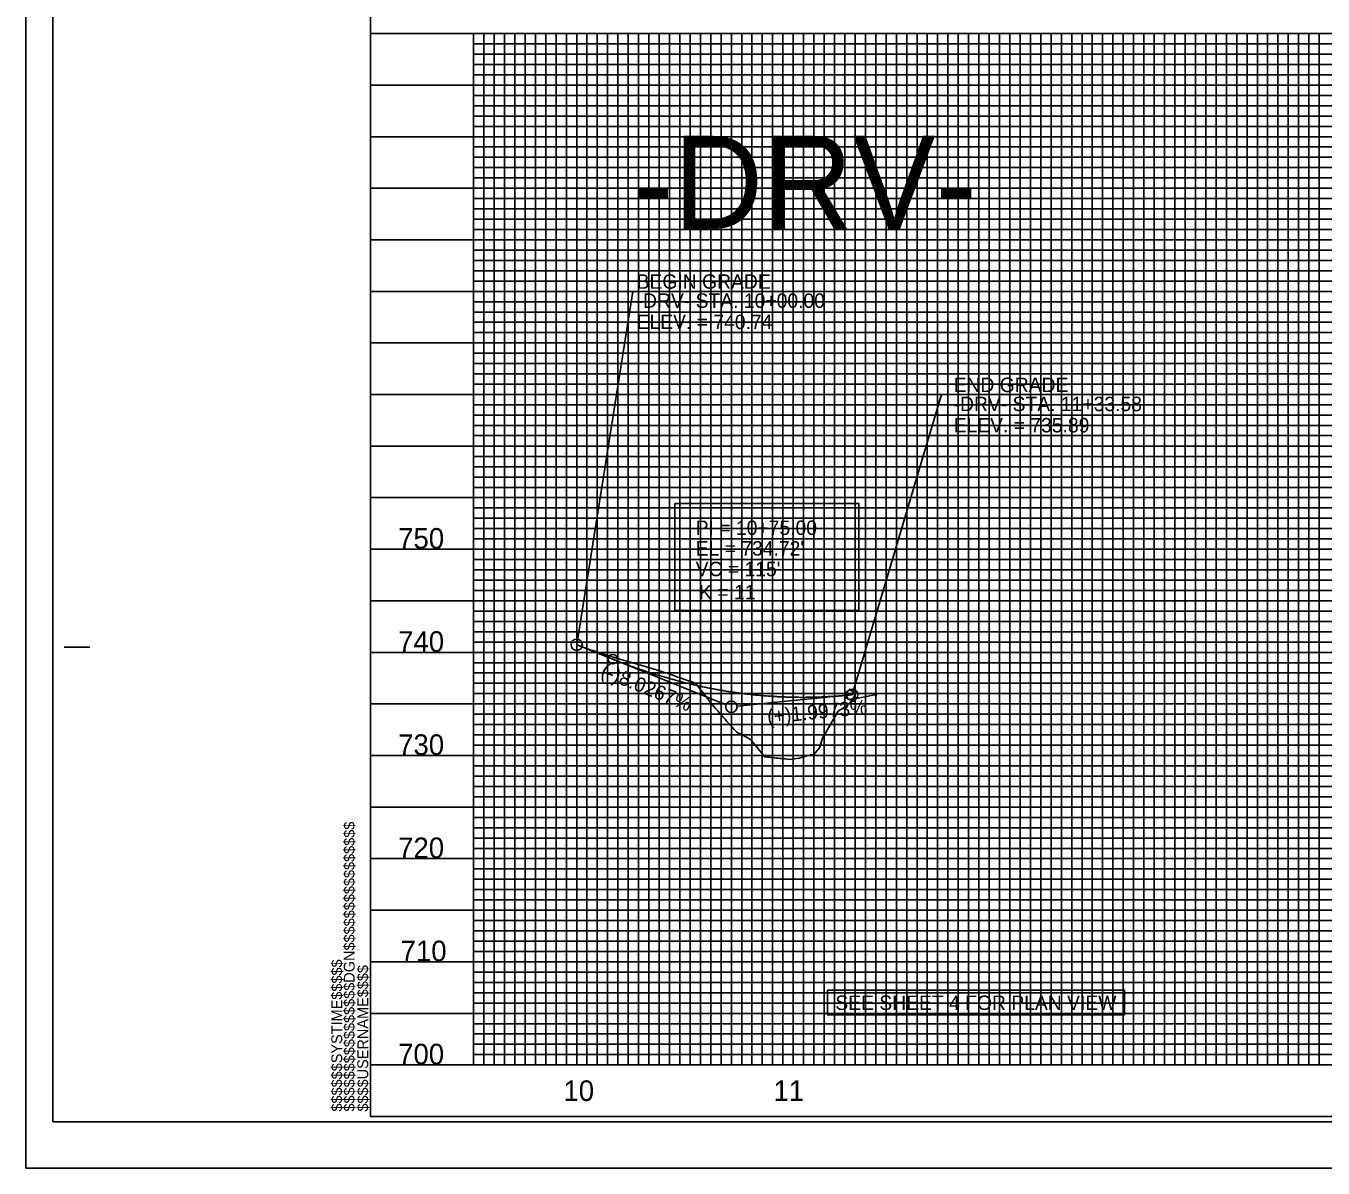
# Model space of a CAD drawing. Extents: x 573926 to 575610, y -51565 to -50465.
# Drawn here: x 573926 to 574555, y -51565 to -51011 of the extents above; entities that cross this region are included whole.
import ezdxf

# ---------------------------------------------------------------- set-up
doc = ezdxf.new("R2010")
doc.units = 0
for name, color, linetype in [('Exist Vertical Profile Ground Line', 7, 'Continuous'), ('Exist Vertical Profile Horizontal Axis Label Major', 7, 'Continuous'), ('Exist Vertical Profile Vertical Axis Label', 7, 'Continuous'), ('Prop Dimension', 7, 'Continuous'), ('Prop Dimension Text', 7, 'Continuous'), ('Prop Grid Mask', 7, 'Continuous'), ('Prop PFL Text', 7, 'Continuous'), ('Prop Vertical Profile Curve Label', 7, 'Continuous'), ('Prop Vertical Profile Grade', 7, 'Continuous'), ('Prop Vertical Profile Grade Label', 7, 'Continuous'), ('Prop VPI Label', 7, 'Continuous'), ('Sheet Cutting Line CELL', 7, 'Continuous'), ('Sheet DOT Grid CELL', 7, 'Continuous'), ('Sheet Layout Profile Border Port 2', 7, 'Continuous'), ('Sheet Plot Border Inside CELL', 7, 'Continuous'), ('Sheet Plot Border Outside CELL', 7, 'Continuous'), ('Sheet Profile CELL', 7, 'Continuous'), ('Sheet Profile Grid Major CELL', 7, 'Continuous'), ('Sheet Profile Grid Middle CELL', 7, 'Continuous'), ('Sheet Profile Grid Minor CELL', 7, 'Continuous')]:
    doc.layers.add(name, color=color, linetype=linetype)

msp = doc.modelspace()

# ---------------------------------------------------------------- linework, layer by layer
at = {"layer": 'Exist Vertical Profile Ground Line'}
for points in [[(574192.78, -51311.24), (574193.67, -51311.6), (574194.55, -51311.96), (574195.44, -51312.32), (574196.33, -51312.66), (574197.22, -51312.95), (574198.11, -51313.24), (574199, -51313.53), (574199.88, -51313.81), (574200.77, -51314.1), (574201.66, -51314.39), (574202.55, -51314.68), (574203.44, -51314.96), (574204.32, -51315.25), (574205.21, -51315.54), (574206.1, -51315.82), (574206.99, -51316.11), (574207.88, -51316.39), (574208.77, -51316.67), (574209.65, -51316.96), (574210.54, -51317.24), (574211.43, -51317.52), (574212.32, -51317.8), (574213.29, -51318.11), (574214.1, -51318.34), (574214.98, -51318.6), (574215.87, -51318.86), (574216.76, -51319.12), (574217.65, -51319.38), (574218.7, -51319.69), (574219.43, -51319.89), (574220.31, -51320.15), (574221.2, -51320.41), (574222.09, -51320.66), (574222.49, -51320.78), (574222.98, -51320.92), (574223.87, -51321.17), (574224.86, -51321.45), (574225.64, -51321.69), (574226.53, -51321.96), (574227.42, -51322.23), (574228.31, -51322.5), (574229.2, -51322.77), (574230.09, -51323.04), (574230.97, -51323.31), (574231.86, -51323.58), (574232.75, -51323.84), (574233.64, -51324.11), (574234.53, -51324.37), (574235.41, -51324.64), (574236.3, -51324.9), (574237.29, -51325.2), (574238.08, -51325.5), (574238.97, -51325.84), (574239.86, -51326.18), (574240.74, -51326.52), (574241.73, -51326.9), (574242.52, -51327.17), (574243.41, -51327.47), (574244.3, -51327.77), (574245.19, -51328.07), (574246.07, -51328.37), (574246.96, -51328.67), (574247.85, -51328.98), (574248.74, -51329.28), (574249.63, -51329.58), (574250.52, -51330), (574251.4, -51331.11), (574252.29, -51332.24), (574253.18, -51333.37), (574254.07, -51334.52), (574254.96, -51335.67), (574255.85, -51336.83), (574256.73, -51338.01), (574257.62, -51339.19), (574258.57, -51340.46), (574259.4, -51341.37), (574260.29, -51342.36), (574261.18, -51343.35), (574262.06, -51344.35), (574262.95, -51345.36), (574263.84, -51346.38), (574264.73, -51347.41), (574265.62, -51348.45), (574266.5, -51349.46), (574267.39, -51350.42), (574268.28, -51351.38), (574269.17, -51352.34), (574270.06, -51353.3), (574270.43, -51353.71), (574270.95, -51353.95), (574271.83, -51354.36), (574272.15, -51354.5), (574272.72, -51354.81), (574273.61, -51355.28), (574274.5, -51355.74), (574275.39, -51356.21), (574276.28, -51356.68), (574277.16, -51357.29), (574278.05, -51358.34), (574278.94, -51359.4)], [(574278.94, -51359.4), (574279.83, -51360.44), (574280.98, -51361.8), (574281.61, -51362.64), (574282.49, -51363.84), (574283.38, -51365.03), (574283.78, -51365.56), (574284.27, -51365.61), (574285.16, -51365.7), (574286.05, -51365.8), (574286.94, -51365.89), (574287.82, -51365.98), (574288.71, -51366.08), (574289.6, -51366.17), (574290.49, -51366.26), (574291.38, -51366.35), (574292.27, -51366.45), (574293.15, -51366.54), (574294.04, -51366.63), (574294.93, -51366.72), (574295.72, -51366.81), (574300.71, -51366.16), (574306.12, -51364.63), (574307.66, -51364.58), (574310.48, -51361.23), (574312.04, -51356.5), (574319.53, -51343.46), (574322.89, -51341.43), (574324.01, -51340.54), (574326.8, -51337.69), (574331.69, -51336.63), (574337.22, -51335.47), (574338.36, -51335.64)]]:
    msp.add_lwpolyline(points, dxfattribs=at)
at = {"layer": 'Prop Dimension'}
for p, q in [((574192.78, -51311.25), (574219.95, -51139.95)), ((574219.95, -51139.95), (574326.21, -51139.95)), ((574326.36, -51335.5), (574369.69, -51189.95)), ((574369.69, -51189.95), (574475.95, -51189.95))]:
    msp.add_line(p, q, dxfattribs=at)
at = {"layer": 'Prop Grid Mask'}
for points in [[(574240.39, -51242.7), (574329.64, -51242.7), (574329.64, -51294.59), (574240.39, -51294.59)], [(574314.32, -51478.65), (574458.42, -51478.65), (574458.42, -51490.63), (574314.32, -51490.63)]]:
    msp.add_lwpolyline(points, close=True, dxfattribs=at)
at = {"layer": 'Prop Vertical Profile Curve Label'}
for centre in [(574210.28, -51318.27), (574325.28, -51335.6)]:
    msp.add_circle(centre, 2.25, dxfattribs=at)
at = {"layer": 'Prop Vertical Profile Grade'}
for p, q in [((574192.78, -51311.25), (574210.28, -51318.27)), ((574325.28, -51335.6), (574326.36, -51335.5))]:
    msp.add_line(p, q, dxfattribs=at)
msp.add_spline([(574210.28, -51318.27), (574212.58, -51319.18), (574214.88, -51320.07), (574217.18, -51320.94), (574219.48, -51321.78), (574221.78, -51322.6), (574224.08, -51323.39), (574226.38, -51324.17), (574228.68, -51324.92), (574230.98, -51325.64), (574233.28, -51326.35), (574235.58, -51327.03), (574237.88, -51327.69), (574240.18, -51328.32), (574242.48, -51328.93), (574244.78, -51329.52), (574247.08, -51330.09), (574249.38, -51330.63), (574251.68, -51331.15), (574253.98, -51331.65), (574256.28, -51332.12), (574258.58, -51332.57), (574260.88, -51333), (574263.18, -51333.4), (574265.48, -51333.78), (574267.78, -51334.14), (574270.08, -51334.48), (574272.38, -51334.79), (574274.68, -51335.08), (574276.98, -51335.34), (574279.28, -51335.59), (574281.58, -51335.81), (574283.88, -51336), (574286.18, -51336.18), (574288.48, -51336.33), (574290.78, -51336.46), (574293.08, -51336.56), (574295.38, -51336.64), (574297.68, -51336.7), (574299.98, -51336.74), (574302.28, -51336.75), (574304.58, -51336.74), (574306.88, -51336.7), (574309.18, -51336.65), (574311.48, -51336.57), (574313.78, -51336.46), (574316.08, -51336.34), (574318.38, -51336.19), (574320.68, -51336.02), (574322.98, -51335.82), (574325.28, -51335.6)], degree=3, dxfattribs=at)
at = {"layer": 'Prop VPI Label'}
for p, q in [((574210.28, -51318.27), (574265.23, -51340.32)), ((574325.28, -51335.6), (574270.51, -51341.07))]:
    msp.add_line(p, q, dxfattribs=at)
for centre in [(574192.78, -51311.25), (574326.36, -51335.5), (574267.78, -51341.35)]:
    msp.add_circle(centre, 2.75, dxfattribs=at)
at = {"layer": 'Sheet Cutting Line CELL'}
for p, q in [((573925.78, -50464.95), (573925.78, -51564.95)), ((573925.78, -51564.95), (575609.78, -51564.95))]:
    msp.add_line(p, q, dxfattribs=at)
at = {"layer": 'Sheet DOT Grid CELL'}
for p, q in [((574092.78, -51014.95), (575592.66, -51014.95)), ((574142.78, -51014.95), (574142.78, -51514.95)), ((574192.78, -51014.95), (574192.78, -51514.95)), ((574242.78, -51014.95), (574242.78, -51514.95)), ((574292.78, -51014.95), (574292.78, -51514.95)), ((574342.78, -51014.95), (574342.78, -51514.95)), ((574392.78, -51014.95), (574392.78, -51514.95)), ((574442.78, -51014.95), (574442.78, -51514.95)), ((574492.78, -51014.95), (574492.78, -51514.95)), ((574542.78, -51014.95), (574542.78, -51514.95)), ((574092.78, -51064.95), (575592.66, -51064.95)), ((574092.78, -51114.95), (575592.66, -51114.95)), ((574092.78, -51164.95), (575592.66, -51164.95)), ((574092.78, -51214.95), (575592.66, -51214.95)), ((574092.78, -51264.95), (575592.66, -51264.95)), ((574092.78, -51314.95), (575592.66, -51314.95)), ((574092.78, -51364.95), (575592.66, -51364.95)), ((574092.78, -51414.95), (575592.66, -51414.95)), ((574092.78, -51464.95), (575592.66, -51464.95))]:
    msp.add_line(p, q, dxfattribs=at)
at = {"layer": 'Sheet Layout Profile Border Port 2'}
msp.add_lwpolyline([(574142.78, -51014.95), (575542.78, -51014.95), (575542.78, -51514.95), (574142.78, -51514.95)], close=True, dxfattribs=at)
at = {"layer": 'Sheet Plot Border Inside CELL'}
msp.add_lwpolyline([(573938.78, -51542.5), (575605.28, -51542.5), (575605.28, -50487.4), (573938.78, -50487.4)], close=True, dxfattribs=at)
at = {"layer": 'Sheet Plot Border Outside CELL'}
msp.add_lwpolyline([(573925.78, -51564.95), (575609.78, -51564.95), (575609.78, -50464.95), (573925.78, -50464.95)], close=True, dxfattribs=at)
at = {"layer": 'Sheet Profile CELL'}
for p, q in [((574092.78, -51014.95), (575592.78, -51014.95)), ((573944.28, -51312.45), (573956.78, -51312.45)), ((575592.78, -51514.95), (574092.78, -51514.95)), ((574092.78, -51539.95), (575592.78, -51539.95)), ((574092.78, -51539.95), (574092.78, -51539.95)), ((574092.78, -51539.95), (574092.78, -51539.95)), ((574092.78, -51539.95), (574092.78, -51539.95)), ((574092.78, -51539.95), (574092.78, -51539.95)), ((574092.78, -51539.95), (574092.78, -51539.95)), ((574092.78, -51539.95), (574092.78, -51539.95)), ((574092.78, -51539.95), (574092.78, -51539.95))]:
    msp.add_line(p, q, dxfattribs=at)
msp.add_lwpolyline([(575592.78, -50489.95), (574092.78, -50489.95), (574092.78, -51539.95), (575592.78, -51539.95)], close=True, dxfattribs=at)
msp.add_lwpolyline([(574130.28, -51539.95), (574130.28, -51539.95)], dxfattribs=at)
at = {"layer": 'Sheet Profile Grid Major CELL'}
msp.add_line((574092.78, -51514.95), (574092.78, -51514.95), dxfattribs=at)
for points in [[(574142.78, -51014.95), (574142.78, -51514.95), (574192.78, -51514.95), (574192.78, -51014.95), (574242.78, -51014.95), (574242.78, -51514.95), (574292.78, -51514.95), (574292.78, -51014.95), (574342.78, -51014.95), (574342.78, -51514.95), (574392.78, -51514.95), (574392.78, -51014.95), (574442.78, -51014.95), (574442.78, -51514.95), (574492.78, -51514.95), (574492.78, -51014.95), (574542.78, -51014.95), (574542.78, -51514.95), (574592.78, -51514.95)], [(575592.78, -51064.95), (574092.78, -51064.95)], [(575592.78, -51114.95), (574092.78, -51114.95), (574092.78, -51164.95), (575592.78, -51164.95)], [(575592.78, -51214.95), (574092.78, -51214.95), (574092.78, -51264.95), (575592.78, -51264.95)], [(575592.78, -51314.95), (574092.78, -51314.95), (574092.78, -51364.95), (575592.78, -51364.95)], [(575592.78, -51414.95), (574092.78, -51414.95), (574092.78, -51414.95), (574092.78, -51464.95), (575592.78, -51464.95)], [(575592.78, -51514.95), (574092.78, -51514.95)]]:
    msp.add_lwpolyline(points, dxfattribs=at)
at = {"layer": 'Sheet Profile Grid Middle CELL'}
for points in [[(574117.78, -51014.95), (574167.78, -51014.95), (574167.78, -51514.95), (574217.78, -51514.95), (574217.78, -51014.95), (574267.78, -51014.95), (574267.78, -51514.95), (574317.78, -51514.95), (574317.78, -51014.95), (574367.78, -51014.95), (574367.78, -51514.95), (574417.78, -51514.95), (574417.78, -51014.95), (574467.78, -51014.95), (574467.78, -51514.95), (574517.78, -51514.95), (574517.78, -51014.95), (574567.78, -51014.95)], [(574092.78, -51039.95), (575592.78, -51039.95)], [(575592.78, -51089.95), (574092.78, -51089.95), (574092.78, -51139.95), (575592.78, -51139.95)], [(575592.78, -51189.95), (574092.78, -51189.95), (574092.78, -51239.95), (575592.78, -51239.95)], [(575592.78, -51289.95), (574092.78, -51289.95), (574092.78, -51339.95), (575592.78, -51339.95)], [(575592.78, -51389.95), (574092.78, -51389.95), (574092.78, -51439.95), (575592.78, -51439.95)], [(575592.78, -51489.95), (574092.78, -51489.95)]]:
    msp.add_lwpolyline(points, dxfattribs=at)
at = {"layer": 'Sheet Profile Grid Minor CELL'}
for p, q in [((574142.78, -51019.95), (575542.78, -51019.95)), ((575542.78, -51024.95), (574142.78, -51024.95)), ((574142.78, -51029.95), (575542.78, -51029.95)), ((575542.78, -51034.95), (574142.78, -51034.95)), ((574142.78, -51044.95), (575542.78, -51044.95)), ((575542.78, -51049.95), (574142.78, -51049.95)), ((574142.78, -51054.95), (575542.78, -51054.95)), ((575542.78, -51059.95), (574142.78, -51059.95)), ((574142.78, -51069.95), (575542.78, -51069.95)), ((575542.78, -51074.95), (574142.78, -51074.95)), ((574142.78, -51079.95), (575542.78, -51079.95)), ((575542.78, -51084.95), (574142.78, -51084.95)), ((574142.78, -51094.95), (575542.78, -51094.95)), ((575542.78, -51099.95), (574142.78, -51099.95)), ((574142.78, -51104.95), (575542.78, -51104.95)), ((575542.78, -51109.95), (574142.78, -51109.95)), ((574142.78, -51119.95), (575542.78, -51119.95)), ((575542.78, -51124.95), (574142.78, -51124.95)), ((574142.78, -51129.95), (575542.78, -51129.95)), ((575542.78, -51134.95), (574142.78, -51134.95)), ((574142.78, -51144.95), (575542.78, -51144.95)), ((575542.78, -51149.95), (574142.78, -51149.95)), ((574142.78, -51154.95), (575542.78, -51154.95)), ((575542.78, -51159.95), (574142.78, -51159.95)), ((574142.78, -51169.95), (575542.78, -51169.95)), ((575542.78, -51174.95), (574142.78, -51174.95)), ((574142.78, -51179.95), (575542.78, -51179.95)), ((575542.78, -51184.95), (574142.78, -51184.95)), ((574142.78, -51194.95), (575542.78, -51194.95)), ((575542.78, -51199.95), (574142.78, -51199.95)), ((574142.78, -51204.95), (575542.78, -51204.95)), ((575542.78, -51209.95), (574142.78, -51209.8)), ((574142.78, -51219.95), (575542.78, -51219.95)), ((575542.78, -51224.95), (574142.78, -51224.95)), ((574142.78, -51229.95), (575542.78, -51229.95)), ((575542.78, -51234.95), (574142.78, -51234.95)), ((574142.78, -51244.95), (575542.78, -51244.95)), ((575542.78, -51249.95), (574142.78, -51249.95)), ((574142.78, -51254.95), (575542.78, -51254.95)), ((575542.78, -51259.95), (574142.78, -51259.95)), ((574142.78, -51269.95), (575542.78, -51269.95)), ((575542.78, -51274.95), (574142.78, -51274.95)), ((574142.78, -51279.95), (575542.78, -51279.95)), ((575542.78, -51284.95), (574142.78, -51284.95)), ((574142.78, -51294.95), (575542.78, -51294.95)), ((575542.78, -51299.95), (574142.78, -51299.95)), ((574142.78, -51304.95), (575542.78, -51304.95)), ((575542.78, -51309.95), (574142.78, -51309.95)), ((574142.78, -51319.95), (575542.78, -51319.95)), ((575542.78, -51324.95), (574142.78, -51324.95)), ((574142.78, -51329.95), (575542.78, -51329.95)), ((575542.78, -51334.95), (574142.78, -51334.95)), ((574142.78, -51344.95), (575542.78, -51344.95)), ((575542.78, -51349.95), (574142.78, -51349.95)), ((574142.78, -51354.95), (575542.78, -51354.95)), ((575542.78, -51359.95), (574142.78, -51359.95)), ((574142.78, -51369.95), (575542.78, -51369.95)), ((575542.78, -51374.95), (574142.78, -51374.95)), ((574142.78, -51379.95), (575542.78, -51379.95)), ((575542.78, -51384.95), (574142.78, -51384.95)), ((574142.78, -51394.95), (575542.78, -51394.95)), ((575542.78, -51399.95), (574142.78, -51399.95)), ((574142.78, -51404.95), (575542.78, -51404.95)), ((575542.78, -51409.95), (574142.78, -51409.95)), ((574142.78, -51419.95), (575542.78, -51419.95)), ((575542.78, -51424.95), (574142.78, -51424.95)), ((574142.78, -51429.95), (575542.78, -51429.95)), ((575542.78, -51434.95), (574142.78, -51434.95)), ((574142.78, -51444.95), (575542.78, -51444.95)), ((575542.78, -51449.95), (574142.78, -51449.95)), ((574142.78, -51454.95), (575542.78, -51454.95)), ((575542.78, -51459.95), (574142.78, -51459.95)), ((574142.78, -51469.95), (575542.78, -51469.95)), ((575542.78, -51474.95), (574142.78, -51474.95)), ((574142.78, -51479.95), (575542.78, -51479.95)), ((575542.78, -51484.95), (574142.78, -51484.95)), ((574142.78, -51494.95), (575542.78, -51494.95)), ((575542.78, -51499.95), (574142.78, -51499.95)), ((574142.78, -51504.95), (575542.78, -51504.95)), ((574142.78, -51509.95), (575542.78, -51509.95))]:
    msp.add_line(p, q, dxfattribs=at)
for points in [[(574142.78, -51014.95), (574147.78, -51014.95), (574147.78, -51514.95), (574152.78, -51514.95), (574152.78, -51014.95), (574157.78, -51014.95), (574157.78, -51514.95), (574162.78, -51514.95), (574162.78, -51014.95), (574172.78, -51014.95), (574172.78, -51514.95), (574177.78, -51514.95), (574177.78, -51014.95), (574182.78, -51014.95), (574182.78, -51514.95), (574187.78, -51514.95), (574197.78, -51514.95), (574202.78, -51514.95), (574202.78, -51014.95), (574207.78, -51014.95), (574207.78, -51514.95), (574212.78, -51514.95), (574212.78, -51014.95), (574222.78, -51014.95), (574222.78, -51514.95), (574227.78, -51514.95), (574227.78, -51014.95), (574232.78, -51014.95), (574232.78, -51514.95), (574237.78, -51514.95), (574237.78, -51014.95), (574247.78, -51014.95), (574247.78, -51514.95), (574252.78, -51514.95), (574252.78, -51014.95), (574257.78, -51014.95), (574257.78, -51514.95), (574262.78, -51514.95), (574262.78, -51014.95), (574272.78, -51014.95), (574272.78, -51514.95), (574277.78, -51514.95), (574277.78, -51014.95), (574282.78, -51014.95), (574282.78, -51514.95), (574287.78, -51514.95), (574287.78, -51014.95), (574297.78, -51014.95), (574297.78, -51514.95), (574302.78, -51514.95), (574302.78, -51014.95), (574307.78, -51014.95), (574307.78, -51514.95), (574312.78, -51514.95), (574312.78, -51014.95), (574322.78, -51014.95), (574322.78, -51514.95), (574327.78, -51514.95), (574327.78, -51014.95), (574332.78, -51014.95), (574332.78, -51514.95), (574337.78, -51514.95), (574337.78, -51014.95), (574347.78, -51014.95), (574347.78, -51514.95), (574352.78, -51514.95), (574352.78, -51014.95), (574357.78, -51014.95), (574357.78, -51514.95)], [(574187.78, -51514.95), (574187.78, -51014.95), (574197.78, -51014.95), (574197.78, -51514.95)], [(574357.78, -51514.95), (574362.78, -51514.95), (574362.78, -51014.95), (574372.78, -51014.95), (574372.78, -51514.95), (574377.78, -51514.95), (574377.78, -51014.95), (574382.78, -51014.95), (574382.78, -51514.95), (574387.78, -51514.95), (574387.78, -51014.95), (574397.78, -51014.95), (574397.78, -51514.95), (574402.78, -51514.95), (574402.78, -51014.95), (574407.78, -51014.95), (574407.78, -51514.95), (574412.78, -51514.95), (574412.78, -51014.95), (574422.78, -51014.95), (574422.78, -51514.95), (574427.78, -51514.95), (574427.78, -51014.95), (574432.78, -51014.95), (574432.78, -51514.95), (574437.78, -51514.95), (574437.78, -51014.95), (574447.78, -51014.95), (574447.78, -51514.95), (574452.78, -51514.95), (574452.78, -51014.95), (574457.78, -51014.95), (574457.78, -51514.95), (574462.78, -51514.95), (574462.78, -51014.95), (574472.78, -51014.95), (574472.78, -51514.95), (574477.78, -51514.95), (574477.78, -51014.95), (574482.78, -51014.95), (574482.78, -51514.95), (574487.78, -51514.95), (574487.78, -51014.95), (574497.78, -51014.95), (574497.78, -51514.95), (574502.78, -51514.95), (574502.78, -51014.95), (574507.78, -51014.95), (574507.78, -51514.95), (574512.78, -51514.95), (574512.78, -51014.95), (574522.78, -51014.95), (574522.78, -51514.95), (574527.78, -51514.95), (574527.78, -51014.95), (574532.78, -51014.95), (574532.78, -51514.95), (574537.78, -51514.95), (574537.78, -51014.95), (574547.78, -51014.95), (574547.78, -51514.95), (574552.78, -51514.95), (574552.78, -51014.95), (574557.78, -51014.95)]]:
    msp.add_lwpolyline(points, dxfattribs=at)

# ---------------------------------------------------------------- texts
at = {"layer": 'Exist Vertical Profile Horizontal Axis Label Major'}
for s, p in [('10', (574186.36, -51532.45)), ('10', (574186.36, -51532.45)), ('11', (574288.2, -51532.45)), ('11', (574288.2, -51532.45))]:
    msp.add_text(s, height=10, dxfattribs=at).set_placement(p)
at = {"layer": 'Exist Vertical Profile Vertical Axis Label'}
for s, p in [('750', (574106.21, -51264.7)), ('740', (574106.21, -51314.7)), ('730', (574106.21, -51364.7)), ('720', (574106.21, -51414.7)), ('710', (574107.41, -51464.7)), ('700', (574106.21, -51514.7))]:
    msp.add_text(s, height=10, dxfattribs=at).set_placement(p)
at = {"layer": 'Prop Dimension Text'}
for s, height, p in [('-DRV-', 45, (574219.72, -51109.52)), ('ELEV. = 740.74', 7, (574221.84, -51158.23)), ('-DRV- STA. 11+33.58', 7, (574375.52, -51198.01)), ('ELEV. = 735.89', 7, (574375.52, -51208.31))]:
    msp.add_text(s, height=height, dxfattribs=at).set_placement(p)
for s, p in [('BEGIN GRADE', (574221.84, -51138.68)), ('-DRV- STA. 10+00.00', (574221.84, -51147.93)), ('END GRADE', (574375.52, -51188.76))]:
    msp.add_text(s, height=7, rotation=360, dxfattribs=at).set_placement(p)
at = {"layer": 'Prop PFL Text'}
msp.add_text('SEE SHEET 4 FOR PLAN VIEW', height=7, dxfattribs=at).set_placement((574318.18, -51488.31))
at = {"layer": 'Prop Vertical Profile Curve Label'}
for s, p in [("VC = 115'", (574250.48, -51278.03)), ('K = 11', (574252.14, -51289.23))]:
    msp.add_text(s, height=7, dxfattribs=at).set_placement(p)
at = {"layer": 'Prop Vertical Profile Grade Label'}
for s, rotation, p in [('(-)8.0267%', 338.13276, (574203.92, -51326.49)), ('(+)1.9973%', 5.70285, (574285.49, -51349.63))]:
    msp.add_text(s, height=7, rotation=rotation, dxfattribs=at).set_placement(p)
at = {"layer": 'Prop VPI Label'}
for s, p in [('PI = 10+75.00', (574250.48, -51258.03)), ("EL = 734.72'", (574250.48, -51268.03))]:
    msp.add_text(s, height=7, dxfattribs=at).set_placement(p)
at = {"layer": 'Sheet Profile CELL'}
for s, p in [('$$$$$$$$$$$$$$$$DGN$$$$$$$$$$$$$$$$', (574085.14, -51537.57)), ('$$$$$$SYSTIME$$$$$', (574079.09, -51537.57)), ('$$$$USERNAME$$$$', (574091.71, -51537.56))]:
    msp.add_text(s, height=5.25, rotation=90, dxfattribs=at).set_placement(p)

doc.saveas('drawing.dxf')
